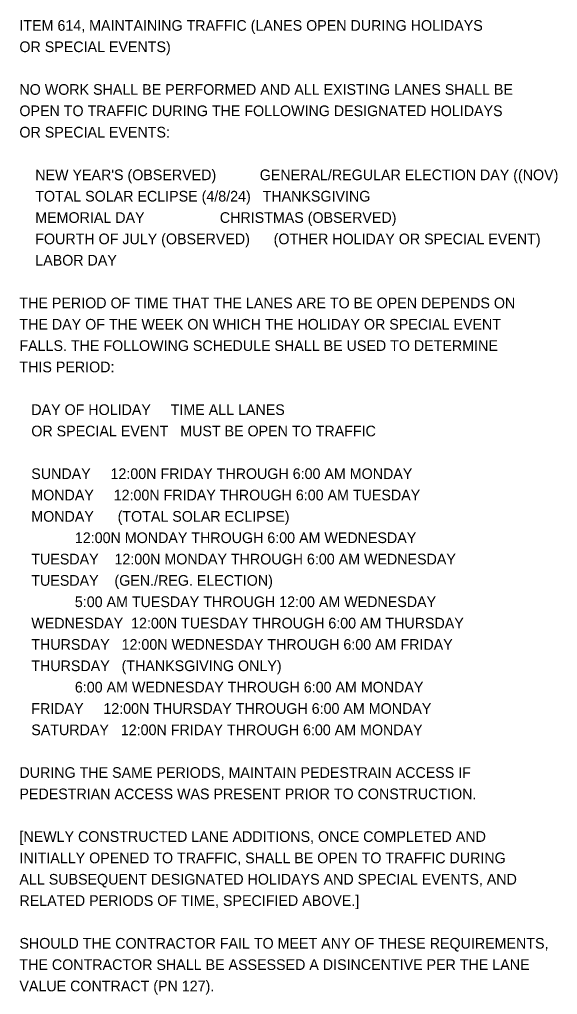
# Model space of a CAD drawing. Extents: x -36 to 68, y -39 to 86.
# Drawn here: x 43.06 to 50.13, y 73.34 to 86.12 of the extents above; entities that cross this region are included whole.
import ezdxf

# ---------------------------------------------------------------- set-up
doc = ezdxf.new("R2010")
doc.units = 0
doc.layers.add('SH_Text', color=7, linetype='Continuous')

msp = doc.modelspace()

# ---------------------------------------------------------------- texts
at = {"layer": 'SH_Text'}
for s, p in [('ITEM 614, MAINTAINING TRAFFIC (LANES OPEN DURING HOLIDAYS', (43.064, 85.977)), ('OR SPECIAL EVENTS)', (43.064, 85.697)), ('NO WORK SHALL BE PERFORMED AND ALL EXISTING LANES SHALL BE', (43.064, 85.137)), ('OPEN TO TRAFFIC DURING THE FOLLOWING DESIGNATED HOLIDAYS', (43.064, 84.857)), ('OR SPECIAL EVENTS:', (43.064, 84.577)), ("    NEW YEAR'S (OBSERVED)           GENERAL/REGULAR ELECTION DAY ((NOV)", (43.064, 84.017)), ('    TOTAL SOLAR ECLIPSE (4/8/24)   THANKSGIVING', (43.064, 83.737)), ('    MEMORIAL DAY                   CHRISTMAS (OBSERVED)', (43.064, 83.457)), ('    FOURTH OF JULY (OBSERVED)      (OTHER HOLIDAY OR SPECIAL EVENT)', (43.064, 83.177)), ('    LABOR DAY', (43.064, 82.897)), ('THE PERIOD OF TIME THAT THE LANES ARE TO BE OPEN DEPENDS ON', (43.064, 82.337)), ('THE DAY OF THE WEEK ON WHICH THE HOLIDAY OR SPECIAL EVENT', (43.064, 82.057)), ('FALLS. THE FOLLOWING SCHEDULE SHALL BE USED TO DETERMINE', (43.064, 81.777)), ('THIS PERIOD:', (43.064, 81.497)), ('   DAY OF HOLIDAY     TIME ALL LANES', (43.064, 80.937)), ('   OR SPECIAL EVENT   MUST BE OPEN TO TRAFFIC', (43.064, 80.657)), ('   SUNDAY     12:00N FRIDAY THROUGH 6:00 AM MONDAY', (43.064, 80.097)), ('   MONDAY     12:00N FRIDAY THROUGH 6:00 AM TUESDAY', (43.064, 79.817)), ('   MONDAY      (TOTAL SOLAR ECLIPSE)', (43.064, 79.537)), ('              12:00N MONDAY THROUGH 6:00 AM WEDNESDAY', (43.064, 79.257)), ('   TUESDAY    12:00N MONDAY THROUGH 6:00 AM WEDNESDAY', (43.064, 78.977)), ('   TUESDAY    (GEN./REG. ELECTION)', (43.064, 78.697)), ('              5:00 AM TUESDAY THROUGH 12:00 AM WEDNESDAY', (43.064, 78.417)), ('   WEDNESDAY  12:00N TUESDAY THROUGH 6:00 AM THURSDAY', (43.064, 78.137)), ('   THURSDAY   12:00N WEDNESDAY THROUGH 6:00 AM FRIDAY', (43.064, 77.857)), ('   THURSDAY   (THANKSGIVING ONLY)', (43.064, 77.577)), ('              6:00 AM WEDNESDAY THROUGH 6:00 AM MONDAY', (43.064, 77.297)), ('   FRIDAY     12:00N THURSDAY THROUGH 6:00 AM MONDAY', (43.064, 77.017)), ('   SATURDAY   12:00N FRIDAY THROUGH 6:00 AM MONDAY', (43.064, 76.737)), ('DURING THE SAME PERIODS, MAINTAIN PEDESTRAIN ACCESS IF', (43.064, 76.177)), ('PEDESTRIAN ACCESS WAS PRESENT PRIOR TO CONSTRUCTION.', (43.064, 75.897)), ('[NEWLY CONSTRUCTED LANE ADDITIONS, ONCE COMPLETED AND', (43.064, 75.337)), ('INITIALLY OPENED TO TRAFFIC, SHALL BE OPEN TO TRAFFIC DURING', (43.064, 75.057)), ('ALL SUBSEQUENT DESIGNATED HOLIDAYS AND SPECIAL EVENTS, AND', (43.064, 74.777)), ('RELATED PERIODS OF TIME, SPECIFIED ABOVE.]', (43.064, 74.497)), ('SHOULD THE CONTRACTOR FAIL TO MEET ANY OF THESE REQUIREMENTS,', (43.064, 73.937)), ('THE CONTRACTOR SHALL BE ASSESSED A DISINCENTIVE PER THE LANE', (43.064, 73.657)), ('VALUE CONTRACT (PN 127).', (43.064, 73.377))]:
    msp.add_text(s, height=0.14, dxfattribs=at).set_placement(p)

doc.saveas('drawing.dxf')
